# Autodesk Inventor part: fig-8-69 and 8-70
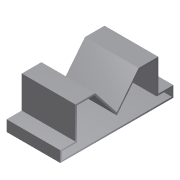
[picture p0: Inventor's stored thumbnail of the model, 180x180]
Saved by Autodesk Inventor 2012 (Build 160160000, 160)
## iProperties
Shininess: 77.0
Length Units: 11269
Angle Units: 11279
Time Units: 11290
Mass Units: 11283
Length Display Precision: 3
Angle Display Precision: 2
Created: 2002-01
Part Number: fig-8-69 and 8-70
Document SubType Name: Modeling
Designer: ***
Density: 1 g/cm^3
Material: Default
Density: 0.0
Volumn: 0.0
Area: 0.0
PropertySet Name: Model Information
Control State: 0
Master: False
Checked Out: False
Author: ***
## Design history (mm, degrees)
node "Sketch1"
sketch "Sketch2"
  geometry: L1 (0, 0)-(-14.184, 17.961); L2 (-14.184, 17.961)-(-26.987, 17.961); L3 (-26.987, 17.961)-(-26.987, -2.947); L4 (-26.987, -2.947)-(-36.842, -2.947); L5 (-36.842, -2.947)-(-36.842, -10.132); L6 (26.987, 17.961)-(26.987, -2.947); L7 (14.184, 17.961)-(26.987, 17.961); L8 (26.987, -2.947)-(36.842, -2.947); L9 (36.842, -10.132)-(-36.842, -10.132); L10 (36.842, -2.947)-(36.842, -10.132); L11 (0, 0)-(14.184, 17.961)
  constraints: 22 end point, 2 horizontal, 2 parallel, 1 perpendicular
extrude "Extrusion1" new body sketch "Sketch2" distance "d0" = 35; taper "d1" = 0 deg
shell "Shell3" dims "d13" = 1
body "Solid1"
